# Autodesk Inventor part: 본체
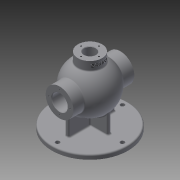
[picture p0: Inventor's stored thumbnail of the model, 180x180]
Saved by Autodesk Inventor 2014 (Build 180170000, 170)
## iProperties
Created: 2020-08
Part Number: 본체
Material: Generic
Document SubType Name: Modeling
Designer: kh
Density: 1 g/cm^3
Appearance: Default
Author: kh
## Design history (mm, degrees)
sketch "Sketch1"
  geometry: C1 r 85 at (0, 0); 1 further point
  constraints: 1 centre point, 1 coincident
  dimensions: "d0" = 170 diameter of C1
extrude "Extrusion1" new body sketch "Sketch1" distance "d1" = 10; taper "d2" = 0 deg
sketch "Sketch2"
  geometry: L1 (0, 0)-(0, 85); L2 (0, 138)-(0, 32); L3 (0, 32)-(0, 0); A1 r 53 centre (0, 85) between (0, 138) and (0, 32)
  constraints: 6 end point, 2 collinear, 2 point on circle, 1 centre point, 1 coincident, 1 midpoint, 1 vertical
  dimensions: "d3" = 85 distance of L1.end L1.start; "d4" = 53 radius of A1
revolve "Revolution1" sketch "Sketch2" stored, may be unused: angle "d5" = 90 deg
sketch "Sketch3"
  geometry: C1 r 53 at (0, 85) reference; C2 r 31 at (0, 85); 1 further point
  constraints: 1 centre point, 1 coincident
  dimensions: "d6" = 62 diameter of C2
extrude "Extrusion2" join sketch "Sketch3" stored distance "d7" = 136; taper "d8" = 0 deg
workplane "Work Plane1"
sketch "Sketch4"
  geometry: C1 r 27 at (0, 0); 1 further point
  constraints: 1 centre point, 1 coincident
  dimensions: "d10" = 54 diameter of C1
extrude "Extrusion3" join sketch "Sketch4" stored distance "d11" = 136; taper "d12" = 0 deg
sketch "Sketch5"
  geometry: L1 (-43, -4)-(43, -4); L2 (43, -4)-(43, 4); L3 (43, 4)-(-43, 4); L4 (-43, 4)-(-43, -4); L5 (-43, -4)-(43, 4); L6 (43, -4)-(-43, 4); L7 (-4, -52)-(4, -52); L8 (4, -52)-(4, 52); L9 (4, 52)-(-4, 52); L10 (-4, 52)-(-4, -52); L11 (-4, -52)-(4, 52); L12 (4, -52)-(-4, 52); 1 further point
  constraints: 24 end point, 4 midpoint, 4 parallel, 2 horizontal, 2 perpendicular
  dimensions: "d13" = 86 distance of L3.end L2.end; "d14" = 8 distance of L2.end L1.end; "d15" = 8 distance of L9.end L8.end; "d16" = 104 distance of L8.end L7.end
extrude "Extrusion4" join sketch "Sketch5" stored distance "d17" = 136; taper "d18" = 0 deg
sketch "Sketch6" dims "d19" = 145
  geometry: C1 r 4.5 at (0, 72.5); 2 further points
  constraints: 2 vertical alignment, 1 centre point, 1 coincident, 2 other
  dimensions: "d20" = 9 diameter of C1
extrude "Extrusion5" cut sketch "Sketch6" stored distance "d21" = 136; taper "d22" = 0 deg
pattern_circular "Circular Pattern1" dims angle "d24" = 360 deg
sketch "Sketch7"
  geometry: C1 r 31 at (0, 0) reference; C2 r 17.5 at (0, 0); 1 further point
  constraints: 1 centre point, 1 coincident
  dimensions: "d26" = 35 diameter of C2
extrude "Extrusion6" cut sketch "Sketch7" stored distance "d27" = 136; taper "d28" = 0 deg
sketch "Sketch8"
  geometry: L1 (0, 0)-(0, 138); L2 (-13, 125.988)-(-13, 150); L3 (-27, 130.607)-(27, 130.607) reference; L4 (-27, 150)-(27, 150) reference; L5 (-13, 150)-(0, 150); L6 (0, 150)-(0, 42); A1 r 53 centre (0, 85) between (42.988, 116) and (-42.988, 116) reference; A2 r 43 centre (0, 85) between (-13, 125.988) and (0, 42)
  constraints: 8 end point, 3 point on circle, 1 centre point, 1 coincident, 1 collinear, 1 midpoint, 1 parallel, 1 point on line
  dimensions: "d29" = 43 radius of A2; "d30" = 26 diameter of L2 L1
revolve "Revolution2" sketch "Sketch8" stored, may be unused: angle "d31" = 90 deg
sketch "Sketch10"
  geometry: L1 (0, 0)-(0, 20); 1 further point
  constraints: 2 end point, 1 coincident, 1 vertical
  dimensions: "d36" = 20 distance of L1.start L1.end
hole "Hole1" sketch "Sketch10" at (0, 20) diameter "d37" = 3.242; stored, may be unused: countersink angle "d41" = 90 deg, drill point angle "d43" = 118 deg; dims "d38" = 12, "d39" = 4, "d40" = 2, "d42" = 15
pattern_circular "Circular Pattern2" dims angle "d45" = 360 deg
sketch "Sketch11"
  geometry: L1 (0, 0)-(0, 24); C1 r 31 at (0, 0) reference; 2 further points
  constraints: 2 end point, 1 coincident, 1 vertical
  dimensions: "d47" = 24 distance of L1.start L1.end
hole "Hole2" sketch "Sketch11" at (0, 24) diameter "d48" = 3.242; stored, may be unused: countersink angle "d52" = 90 deg, drill point angle "d54" = 118 deg; dims "d49" = 12, "d50" = 4, "d51" = 2, "d53" = 15
pattern_circular "Circular Pattern3" dims angle "d56" = 360 deg
mirror "Mirror1"
workplane "Work Plane2"
sketch "Sketch12"
  geometry: L1 (-20.016, -2.862)-(20.016, -2.862); L2 (20.016, -2.862)-(20.016, -15.138); L3 (20.016, -15.138)-(-20.016, -15.138); L4 (-20.016, -15.138)-(-20.016, -2.862); L5 (-20.016, -15.138)-(20.016, -2.862); L6 (-27, 0)-(27, 0) reference; 2 further points
  constraints: 2 end point, 1 midpoint, 2 other
  dimensions: "d58" = 9 distance from line of point (0, -9) L6; "d59" = 27 horizontal distance of point (0, -9) L6.start
emboss "Emboss1" sketch "Sketch12" dims "d60" = 0.5, "d61" = 0
fillet "Fillet1" dims "d62" = 3
fillet "Fillet2" dims "d63" = 3
fillet "Fillet3" dims "d64" = 3
fillet "Fillet4" dims "d65" = 3
chamfer "Chamfer1" distance "d66" = 1; stored, may be unused: second distance "d67" = 2, angle "d68" = 45 deg
sketch "Sketch13"
  geometry: L1 (39.278, 102.5)-(39.278, 67.5) reference; L2 (67, 102.5)-(67, 67.5) reference; L3 (68, 66.5)-(68, 103.5) reference; L4 (39.278, 85)-(68, 85); L5 (52, 85)-(50.25, 85); L6 (50.25, 85)-(50.25, 66.5); L7 (50.25, 66.5)-(52, 66.5); L8 (52, 66.5)-(52, 85); 1 further point
  constraints: 10 end point, 2 midpoint, 2 parallel, 1 horizontal, 1 perpendicular, 1 point on line
  dimensions: "d69" = 16 distance between parallel lines of L3 L8; "d70" = 1.75 distance of L6.end L7.end; "d71" = 37 diameter of L7 L4
revolve "Revolution4" sketch "Sketch13" stored, may be unused: angle "d72" = 90 deg
body "Solid1"
node "Projected Loop1"
node "Projected Loop2"
node "Projected Loop4"
